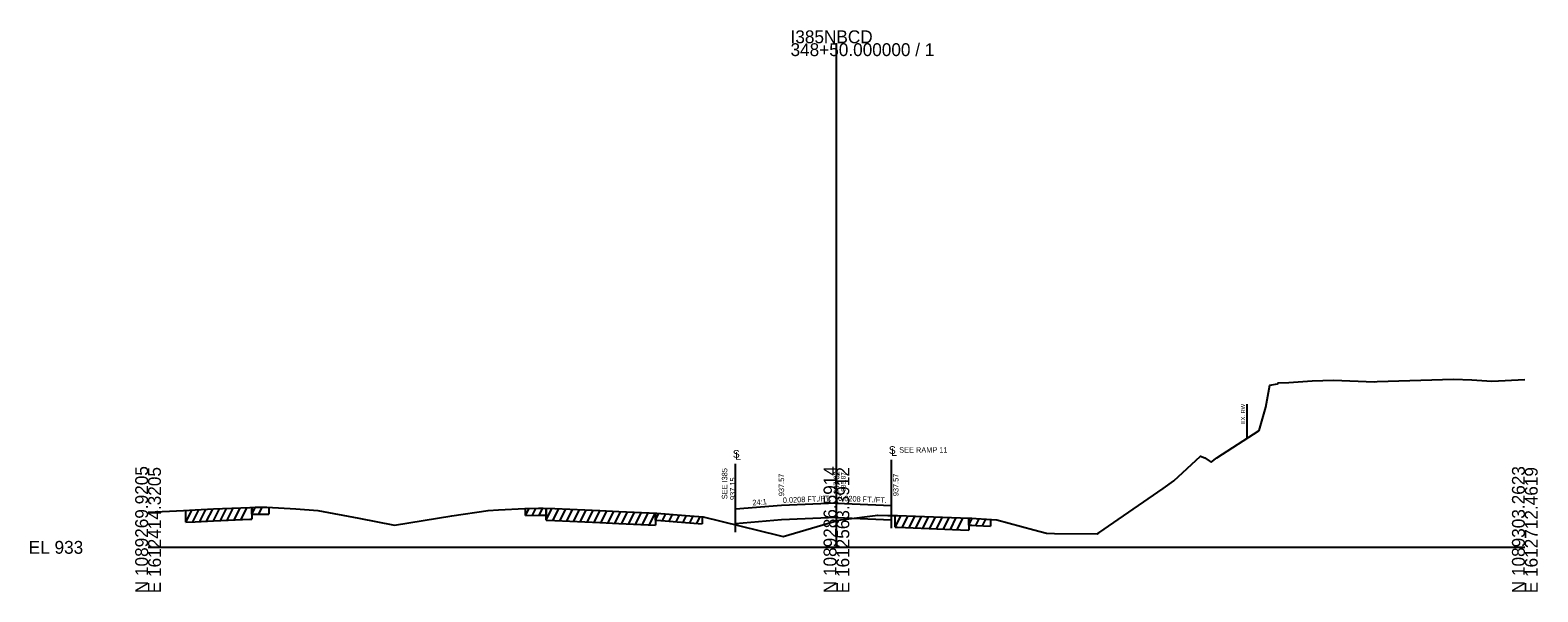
# Model space of a CAD drawing. Extents: x -26 to 1613369, y -10 to 1281970.
# Drawn here: x -25.7 to 302.8, y 17990.3 to 18112.6 of the extents above; entities that cross this region are included whole.
import ezdxf

# ---------------------------------------------------------------- set-up
doc = ezdxf.new("R2010")
doc.units = 0
for name, color, linetype in [('RD_EX_Misc', 7, 'Continuous'), ('RD_GPK_XS_Cell', 7, 'Continuous'), ('RD_Sketch1', 7, 'Continuous'), ('RD_XS_Base', 7, 'Continuous'), ('RD_XS_ExGround', 7, 'Continuous'), ('RD_XS_ExPaveRet', 7, 'Continuous'), ('RD_XS_ExRW', 7, 'Continuous'), ('RD_XS_MatchLine', 7, 'Continuous'), ('RD_XS_Pave', 7, 'Continuous'), ('RD_XS_PaveShd', 7, 'Continuous'), ('RD_XS_TX_Elev_EX', 7, 'Continuous'), ('RD_XS_TX_Elev_PR', 7, 'Continuous'), ('RD_XS_TX_MatchLine', 7, 'Continuous'), ('RD_XS_TX_Notes', 7, 'Continuous'), ('RD_XS_TX_ShdSlope', 7, 'Continuous'), ('RD_XS_TX_Slope', 7, 'Continuous')]:
    doc.layers.add(name, color=color, linetype=linetype)

msp = doc.modelspace()

# ---------------------------------------------------------------- linework, layer by layer
at = {"layer": 'RD_EX_Misc'}
for p, q in [((22.63, 18007.22), (22.63, 18008.72)), ((22.63, 18007.22), (23.36, 18007.23)), ((23.36, 18007.23), (25.88, 18007.24)), ((25.88, 18007.24), (26.35, 18007.21)), ((26.35, 18008.71), (26.35, 18007.21)), ((82.25, 18006.93), (82.25, 18008.43)), ((82.25, 18006.93), (85.05, 18007.01)), ((85.05, 18007.01), (86.12, 18007.04)), ((86.12, 18007.04), (86.72, 18007.02)), ((86.72, 18008.52), (86.72, 18007.02)), ((110.58, 18005.93), (110.58, 18007.43)), ((110.58, 18005.93), (110.83, 18005.91)), ((110.83, 18005.91), (117.13, 18005.42)), ((117.13, 18005.42), (120.72, 18005.14)), ((120.72, 18006.64), (120.72, 18005.14)), ((178.85, 18004.86), (178.85, 18006.36)), ((178.85, 18004.86), (179.52, 18004.83)), ((179.52, 18004.83), (180.48, 18004.76)), ((180.48, 18004.76), (183.6, 18004.58)), ((183.6, 18006.08), (183.6, 18004.58))]:
    msp.add_line(p, q, dxfattribs=at)
at = {"layer": 'RD_GPK_XS_Cell'}
for p, q in [((150, 18000), (150, 18109.79)), ((0, 18000), (150, 18000)), ((150, 18000), (300, 18000))]:
    msp.add_line(p, q, dxfattribs=at)
at = {"layer": 'RD_Sketch1'}
for p, q in [((22.63, 18007.22), (23.39, 18008.73)), ((24.13, 18007.24), (24.88, 18008.74)), ((82.25, 18006.93), (83.01, 18008.45)), ((83.75, 18006.97), (84.51, 18008.49)), ((85.25, 18007.01), (86.01, 18008.54)), ((110.58, 18005.93), (111.3, 18007.38)), ((112.08, 18005.82), (112.8, 18007.26)), ((113.58, 18005.7), (114.3, 18007.14)), ((115.08, 18005.58), (115.8, 18007.03)), ((116.58, 18005.47), (117.3, 18006.91)), ((118.08, 18005.35), (118.8, 18006.79)), ((119.58, 18005.23), (120.3, 18006.67)), ((178.85, 18004.86), (179.59, 18006.32)), ((180.35, 18004.77), (181.08, 18006.23)), ((181.85, 18004.68), (182.58, 18006.14))]:
    msp.add_line(p, q, dxfattribs=at)
at = {"layer": 'RD_XS_Base'}
for p, q in [((162, 18005.97), (162, 18006.96)), ((138, 18005.97), (128, 18005.14)), ((150, 18006.47), (138, 18005.97)), ((150, 18006.47), (162, 18005.97))]:
    msp.add_line(p, q, dxfattribs=at)
at = {"layer": 'RD_XS_ExGround'}
msp.add_lwpolyline([(0, 18007.67), (7.73, 18008.04), (10.3, 18008.16), (14.23, 18008.35), (22.18, 18008.71), (23.36, 18008.73), (25.88, 18008.74), (32.21, 18008.35), (36.98, 18008.04), (45.9, 18006.35), (53.72, 18004.86), (66.17, 18006.83), (74.12, 18008), (76.33, 18008.17), (82.09, 18008.42), (85.05, 18008.51), (86.12, 18008.54), (88.62, 18008.43), (98.46, 18008.01), (102.55, 18007.82), (110.83, 18007.41), (117.13, 18006.92), (120.93, 18006.62), (137.2, 18002.68), (138.42, 18002.39), (147.02, 18004.88), (150, 18005.74), (150.61, 18005.92), (150.93, 18005.96), (158.99, 18006.98), (161.23, 18006.96), (163.29, 18006.96), (177.06, 18006.43), (179.52, 18006.33), (180.48, 18006.26), (184.96, 18005.99), (193.03, 18003.82), (195.79, 18003.11), (197.53, 18003.01), (206.79, 18002.97), (207.18, 18003.19), (221.21, 18012.78), (223.52, 18014.51), (229.31, 18019.84), (230.28, 18019.49), (231.22, 18018.86), (231.66, 18018.56), (232.9, 18019.47), (242.11, 18025.45), (243.54, 18030.49), (244.41, 18035.33), (246.14, 18035.63), (246.22, 18035.81), (246.32, 18035.85), (248.6, 18035.93), (253.66, 18036.25), (258.33, 18036.41), (267.28, 18036.06), (267.84, 18036.08), (284.46, 18036.6), (288.45, 18036.51), (292.82, 18036.2), (300, 18036.52)], dxfattribs=at)
at = {"layer": 'RD_XS_ExPaveRet'}
for p, q in [((8.25, 18005.46), (9.58, 18008.13)), ((8.25, 18005.46), (8.25, 18008.06)), ((9.75, 18005.54), (11.08, 18008.2)), ((11.25, 18005.61), (12.58, 18008.27)), ((12.75, 18005.68), (14.08, 18008.34)), ((14.25, 18005.75), (15.58, 18008.41)), ((15.75, 18005.82), (17.08, 18008.48)), ((17.25, 18005.89), (18.58, 18008.55)), ((18.75, 18005.95), (20.08, 18008.61)), ((20.25, 18006.02), (21.58, 18008.68)), ((22.63, 18008.72), (22.63, 18006.12)), ((86.72, 18005.92), (86.72, 18008.52)), ((86.72, 18005.92), (88, 18008.46)), ((88.22, 18005.85), (89.5, 18008.39)), ((89.72, 18005.79), (91, 18008.33)), ((91.22, 18005.72), (92.5, 18008.27)), ((92.72, 18005.66), (94, 18008.2)), ((94.22, 18005.59), (95.5, 18008.14)), ((95.72, 18005.53), (97, 18008.07)), ((97.23, 18005.47), (98.5, 18008.01)), ((98.73, 18005.4), (100, 18007.94)), ((100.23, 18005.33), (101.5, 18007.87)), ((101.73, 18005.26), (103, 18007.8)), ((103.23, 18005.19), (104.49, 18007.73)), ((104.73, 18005.11), (106, 18007.65)), ((106.23, 18005.04), (107.5, 18007.58)), ((107.73, 18004.97), (109, 18007.5)), ((109.23, 18004.89), (110.5, 18007.43)), ((110.58, 18007.43), (110.58, 18004.83)), ((162.82, 18004.36), (162.82, 18006.96)), ((162.82, 18004.36), (164.1, 18006.93)), ((164.32, 18004.32), (165.6, 18006.87)), ((8.25, 18005.46), (10.3, 18005.56)), ((10.3, 18005.56), (14.23, 18005.75)), ((14.23, 18005.75), (22.18, 18006.11)), ((22.18, 18006.11), (22.63, 18006.12)), ((86.72, 18005.92), (88.62, 18005.83)), ((88.62, 18005.83), (98.46, 18005.41)), ((98.46, 18005.41), (102.55, 18005.22)), ((102.55, 18005.22), (110.58, 18004.83)), ((162.82, 18004.36), (163.29, 18004.36)), ((163.29, 18004.36), (177.06, 18003.83)), ((165.82, 18004.26), (167.1, 18006.81)), ((167.32, 18004.21), (168.6, 18006.76)), ((168.82, 18004.15), (170.1, 18006.7)), ((170.32, 18004.09), (171.6, 18006.64)), ((171.82, 18004.03), (173.1, 18006.58)), ((173.32, 18003.97), (174.6, 18006.52)), ((174.82, 18003.91), (176.1, 18006.46)), ((176.32, 18003.86), (177.6, 18006.41)), ((177.06, 18003.83), (178.85, 18003.76)), ((178.85, 18006.36), (178.85, 18003.76))]:
    msp.add_line(p, q, dxfattribs=at)
at = {"layer": 'RD_XS_ExRW'}
msp.add_line((239.41, 18031.21), (239.41, 18023.69), dxfattribs=at)
at = {"layer": 'RD_XS_MatchLine'}
for p, q in [((128, 18004.91), (128, 18008.31)), ((162, 18006.96), (162, 18009.14))]:
    msp.add_line(p, q, dxfattribs=at)
at = {"layer": 'RD_XS_Pave'}
for q in [(138, 18009.14), (162, 18009.14)]:
    msp.add_line((150, 18009.64), q, dxfattribs=at)
at = {"layer": 'RD_XS_PaveShd'}
msp.add_line((138, 18009.14), (128, 18008.31), dxfattribs=at)
msp.add_line((138, 18009.14), (128, 18008.31), dxfattribs=at)
at = {"layer": 'RD_XS_TX_MatchLine'}
for p, q in [((128, 18008.31), (128, 18018.19)), ((162, 18009.14), (162, 18019.03)), ((128, 18003.31), (128, 18008.31)), ((162, 18004.14), (162, 18009.14))]:
    msp.add_line(p, q, dxfattribs=at)

# ---------------------------------------------------------------- texts
at = {"layer": 'RD_GPK_XS_Cell'}
for s, p in [('I385NBCD', (140, 18109.79)), ('348+50.000000 / 1', (140, 18106.99)), ('EL 933', (-26, 17998.6))]:
    msp.add_text(s, height=2.8, dxfattribs=at).set_placement(p)
for s, p in [('N 1089269.9205', (0, 17990)), ('E 1612414.3205', (2.8, 17990)), ('N 1089286.5914', (150, 17990)), ('E 1612563.3912', (152.8, 17990)), ('N 1089303.2623', (300, 17990)), ('E 1612712.4619', (302.8, 17990))]:
    msp.add_text(s, height=2.8, rotation=90, dxfattribs=at).set_placement(p)
at = {"layer": 'RD_XS_ExRW'}
msp.add_text('EX. RW', height=0.9, rotation=90, dxfattribs=at).set_placement((239.05, 18026.81))
at = {"layer": 'RD_XS_TX_Elev_EX'}
msp.add_text('935.87', height=1, rotation=90, dxfattribs=at).set_placement((152, 18012.13))
at = {"layer": 'RD_XS_TX_Elev_PR'}
for s, p in [('937.15', (128, 18010.31)), ('937.57', (138.6, 18011.14)), ('937.82', (150.6, 18011.64)), ('937.57', (163.52, 18011.14))]:
    msp.add_text(s, height=1.2, rotation=90, dxfattribs=at).set_placement(p)
at = {"layer": 'RD_XS_TX_MatchLine'}
for s, p in [('S', (127.42, 18019.51)), ('L', (127.93, 18019.07)), ('S', (161.42, 18020.34)), ('L', (161.93, 18019.91))]:
    msp.add_text(s, height=1.68, dxfattribs=at).set_placement(p)
at = {"layer": 'RD_XS_TX_Notes'}
msp.add_text('SEE RAMP 11', height=1.2, dxfattribs=at).set_placement((163.68, 18020.61))
msp.add_text('SEE I385', height=1.2, rotation=90, dxfattribs=at).set_placement((126.23, 18010.47))
at = {"layer": 'RD_XS_TX_ShdSlope'}
msp.add_text('24:1', height=1.2, rotation=4.7636, dxfattribs=at).set_placement((131.75, 18009.12))
at = {"layer": 'RD_XS_TX_Slope'}
for rotation, p in [(2.3859, (138.34, 18009.65)), (357.6141, (150.35, 18010.12))]:
    msp.add_text('0.0208 FT./FT.', height=1.2, rotation=rotation, dxfattribs=at).set_placement(p)

doc.saveas('drawing.dxf')
